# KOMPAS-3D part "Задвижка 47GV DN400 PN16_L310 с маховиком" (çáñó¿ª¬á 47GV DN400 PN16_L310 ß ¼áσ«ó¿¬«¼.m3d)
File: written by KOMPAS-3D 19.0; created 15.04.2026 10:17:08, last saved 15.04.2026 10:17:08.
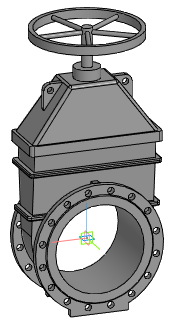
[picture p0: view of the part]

Document properties: Автор: Евгений; Полное имя файла: Z:\3.Личные\kachalov\3d для проектировщиков\2.1 Тип 47GV, 47GV.Z\Задвижка 47GV_DN40-DN600\stp_Задвижка 47GV\Задвижка 47GV DN400 PN16_L310 с маховиком.m3d

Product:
- Part/product: Задвижка 47GV DN400 PN16_L310 с маховиком

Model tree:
1. Операция без истории:1  (labels: Задвижка 47GV DN400 PN16_L310 с маховиком)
